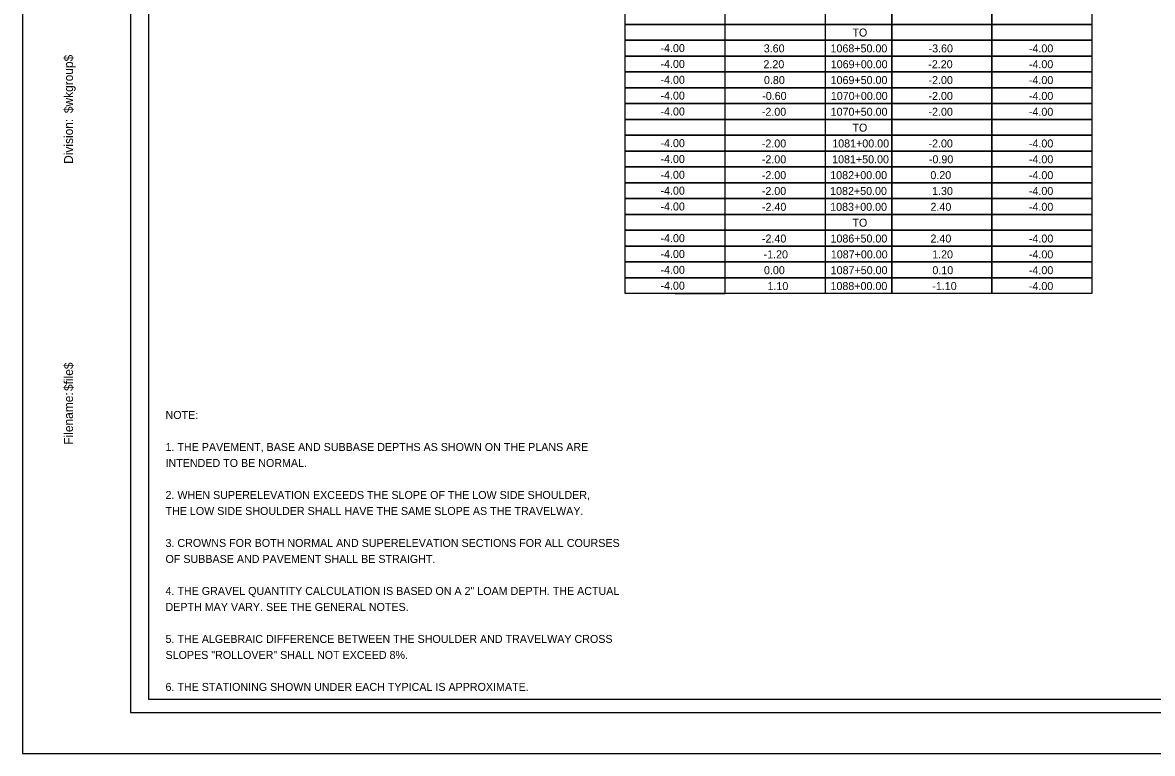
# Model space of a CAD drawing. Extents: x 1026502 to 1027102, y 781811 to 782040.
# Drawn here: x 1026618.9 to 1026686.7, y 781854.4 to 781898.3 of the extents above; entities that cross this region are included whole.
import ezdxf

# ---------------------------------------------------------------- set-up
doc = ezdxf.new("R2010")
doc.units = 0
for name, color, linetype in [('ANNOTATION', 7, 'Continuous'), ('BORDER', 7, 'Continuous'), ('DIMENSIONS', 7, 'Continuous'), ('JUNK', 7, 'Continuous'), ('PLOT BOUNDARY', 7, 'Continuous')]:
    doc.layers.add(name, color=color, linetype=linetype)

msp = doc.modelspace()

# ---------------------------------------------------------------- linework, layer by layer
at = {"layer": 'ANNOTATION'}
msp.add_lwpolyline([(1026655.027, 781936.19), (1026683.027, 781936.19), (1026683.027, 781882.017), (1026655.027, 781882.017)], close=True, dxfattribs=at)
at = {"layer": 'BORDER'}
for p, q in [((1026625.357, 781940.868), (1026625.357, 781856.868)), ((1026658.027, 781898.174), (1026655.027, 781898.174)), ((1026658.027, 781898.174), (1026655.027, 781898.174)), ((1026658.027, 781898.174), (1026661.027, 781898.174)), ((1026658.027, 781897.223), (1026655.027, 781897.223)), ((1026658.027, 781897.223), (1026655.027, 781897.223)), ((1026658.027, 781897.223), (1026661.027, 781897.223)), ((1026658.027, 781896.273), (1026655.027, 781896.273)), ((1026658.027, 781896.273), (1026655.027, 781896.273)), ((1026658.027, 781896.273), (1026661.027, 781896.273)), ((1026658.027, 781895.322), (1026655.027, 781895.322)), ((1026658.027, 781895.322), (1026655.027, 781895.322)), ((1026658.027, 781895.322), (1026661.027, 781895.322)), ((1026658.027, 781894.372), (1026655.027, 781894.372)), ((1026658.027, 781894.372), (1026655.027, 781894.372)), ((1026658.027, 781894.372), (1026661.027, 781894.372)), ((1026658.027, 781893.422), (1026655.027, 781893.422)), ((1026658.027, 781893.422), (1026655.027, 781893.422)), ((1026658.027, 781893.422), (1026661.027, 781893.422)), ((1026658.027, 781892.471), (1026655.027, 781892.471)), ((1026658.027, 781892.471), (1026655.027, 781892.471)), ((1026658.027, 781892.471), (1026661.027, 781892.471)), ((1026658.027, 781891.521), (1026655.027, 781891.521)), ((1026658.027, 781891.521), (1026655.027, 781891.521)), ((1026658.027, 781891.521), (1026661.027, 781891.521)), ((1026658.027, 781890.57), (1026655.027, 781890.57)), ((1026658.027, 781890.57), (1026655.027, 781890.57)), ((1026658.027, 781890.57), (1026661.027, 781890.57)), ((1026658.027, 781889.62), (1026655.027, 781889.62)), ((1026658.027, 781889.62), (1026655.027, 781889.62)), ((1026658.027, 781889.62), (1026661.027, 781889.62)), ((1026658.027, 781888.67), (1026655.027, 781888.67)), ((1026658.027, 781888.67), (1026655.027, 781888.67)), ((1026658.027, 781888.67), (1026661.027, 781888.67)), ((1026658.027, 781887.719), (1026655.027, 781887.719)), ((1026658.027, 781887.719), (1026655.027, 781887.719)), ((1026658.027, 781887.719), (1026661.027, 781887.719)), ((1026658.027, 781886.769), (1026655.027, 781886.769)), ((1026658.027, 781886.769), (1026655.027, 781886.769)), ((1026658.027, 781886.769), (1026661.027, 781886.769)), ((1026658.027, 781885.818), (1026655.027, 781885.818)), ((1026658.027, 781885.818), (1026655.027, 781885.818)), ((1026658.027, 781885.818), (1026661.027, 781885.818)), ((1026658.027, 781884.868), (1026655.027, 781884.868)), ((1026658.027, 781884.868), (1026655.027, 781884.868)), ((1026658.027, 781884.868), (1026661.027, 781884.868)), ((1026658.027, 781883.918), (1026655.027, 781883.918)), ((1026658.027, 781883.918), (1026655.027, 781883.918)), ((1026658.027, 781883.918), (1026661.027, 781883.918)), ((1026658.027, 781882.967), (1026655.027, 781882.967)), ((1026658.027, 781882.967), (1026655.027, 781882.967)), ((1026658.027, 781882.967), (1026661.027, 781882.967)), ((1026658.027, 781882.017), (1026655.027, 781882.017)), ((1026658.027, 781882.017), (1026655.027, 781882.017)), ((1026658.027, 781882.017), (1026661.027, 781882.017)), ((1026625.357, 781856.868), (1026753.357, 781856.868))]:
    msp.add_line(p, q, dxfattribs=at)
for points in [[(1026655.027, 781899.124), (1026683.027, 781899.124), (1026683.027, 781898.174), (1026655.027, 781898.174)], [(1026655.027, 781898.174), (1026683.027, 781898.174), (1026683.027, 781897.223), (1026655.027, 781897.223)], [(1026655.027, 781897.223), (1026683.027, 781897.223), (1026683.027, 781896.273), (1026655.027, 781896.273)], [(1026655.027, 781896.273), (1026683.027, 781896.273), (1026683.027, 781895.322), (1026655.027, 781895.322)], [(1026655.027, 781895.322), (1026683.027, 781895.322), (1026683.027, 781894.372), (1026655.027, 781894.372)], [(1026655.027, 781894.372), (1026683.027, 781894.372), (1026683.027, 781893.422), (1026655.027, 781893.422)], [(1026655.027, 781893.422), (1026683.027, 781893.422), (1026683.027, 781892.471), (1026655.027, 781892.471)], [(1026655.027, 781892.471), (1026683.027, 781892.471), (1026683.027, 781891.521), (1026655.027, 781891.521)], [(1026655.027, 781891.521), (1026683.027, 781891.521), (1026683.027, 781890.57), (1026655.027, 781890.57)], [(1026655.027, 781890.57), (1026683.027, 781890.57), (1026683.027, 781889.62), (1026655.027, 781889.62)], [(1026655.027, 781889.62), (1026683.027, 781889.62), (1026683.027, 781888.67), (1026655.027, 781888.67)], [(1026655.027, 781888.67), (1026683.027, 781888.67), (1026683.027, 781887.719), (1026655.027, 781887.719)], [(1026655.027, 781887.719), (1026683.027, 781887.719), (1026683.027, 781886.769), (1026655.027, 781886.769)], [(1026655.027, 781886.769), (1026683.027, 781886.769), (1026683.027, 781885.818), (1026655.027, 781885.818)], [(1026655.027, 781885.818), (1026683.027, 781885.818), (1026683.027, 781884.868), (1026655.027, 781884.868)], [(1026655.027, 781884.868), (1026683.027, 781884.868), (1026683.027, 781883.918), (1026655.027, 781883.918)], [(1026655.027, 781883.918), (1026683.027, 781883.918), (1026683.027, 781882.967), (1026655.027, 781882.967)], [(1026655.027, 781882.967), (1026683.027, 781882.967), (1026683.027, 781882.017), (1026655.027, 781882.017)]]:
    msp.add_lwpolyline(points, close=True, dxfattribs=at)
for points in [[(1026667.027, 781899.124), (1026667.027, 781898.174), (1026661.027, 781898.174), (1026661.027, 781899.124)], [(1026671.027, 781899.124), (1026671.027, 781898.174), (1026667.027, 781898.174)], [(1026677.027, 781899.124), (1026677.027, 781898.174), (1026671.027, 781898.174), (1026671.027, 781899.124)], [(1026683.027, 781899.124), (1026683.027, 781898.174), (1026677.027, 781898.174), (1026677.027, 781899.124)], [(1026667.027, 781898.174), (1026667.027, 781897.223), (1026661.027, 781897.223), (1026661.027, 781898.174)], [(1026671.027, 781898.174), (1026671.027, 781897.223), (1026667.027, 781897.223)], [(1026677.027, 781898.174), (1026677.027, 781897.223), (1026671.027, 781897.223), (1026671.027, 781898.174)], [(1026683.027, 781898.174), (1026683.027, 781897.223), (1026677.027, 781897.223), (1026677.027, 781898.174)], [(1026667.027, 781897.223), (1026667.027, 781896.273), (1026661.027, 781896.273), (1026661.027, 781897.223)], [(1026671.027, 781897.223), (1026671.027, 781896.273), (1026667.027, 781896.273)], [(1026677.027, 781897.223), (1026677.027, 781896.273), (1026671.027, 781896.273), (1026671.027, 781897.223)], [(1026683.027, 781897.223), (1026683.027, 781896.273), (1026677.027, 781896.273), (1026677.027, 781897.223)], [(1026667.027, 781896.273), (1026667.027, 781895.322), (1026661.027, 781895.322), (1026661.027, 781896.273)], [(1026671.027, 781896.273), (1026671.027, 781895.322), (1026667.027, 781895.322)], [(1026677.027, 781896.273), (1026677.027, 781895.322), (1026671.027, 781895.322), (1026671.027, 781896.273)], [(1026683.027, 781896.273), (1026683.027, 781895.322), (1026677.027, 781895.322), (1026677.027, 781896.273)], [(1026667.027, 781895.322), (1026667.027, 781894.372), (1026661.027, 781894.372), (1026661.027, 781895.322)], [(1026671.027, 781895.322), (1026671.027, 781894.372), (1026667.027, 781894.372)], [(1026677.027, 781895.322), (1026677.027, 781894.372), (1026671.027, 781894.372), (1026671.027, 781895.322)], [(1026683.027, 781895.322), (1026683.027, 781894.372), (1026677.027, 781894.372), (1026677.027, 781895.322)], [(1026667.027, 781894.372), (1026667.027, 781893.422), (1026661.027, 781893.422), (1026661.027, 781894.372)], [(1026671.027, 781894.372), (1026671.027, 781893.422), (1026667.027, 781893.422)], [(1026677.027, 781894.372), (1026677.027, 781893.422), (1026671.027, 781893.422), (1026671.027, 781894.372)], [(1026683.027, 781894.372), (1026683.027, 781893.422), (1026677.027, 781893.422), (1026677.027, 781894.372)], [(1026667.027, 781893.422), (1026667.027, 781892.471), (1026661.027, 781892.471), (1026661.027, 781893.422)], [(1026671.027, 781893.422), (1026671.027, 781892.471), (1026667.027, 781892.471)], [(1026677.027, 781893.422), (1026677.027, 781892.471), (1026671.027, 781892.471), (1026671.027, 781893.422)], [(1026683.027, 781893.422), (1026683.027, 781892.471), (1026677.027, 781892.471), (1026677.027, 781893.422)], [(1026667.027, 781892.471), (1026667.027, 781891.521), (1026661.027, 781891.521), (1026661.027, 781892.471)], [(1026671.027, 781892.471), (1026671.027, 781891.521), (1026667.027, 781891.521)], [(1026677.027, 781892.471), (1026677.027, 781891.521), (1026671.027, 781891.521), (1026671.027, 781892.471)], [(1026683.027, 781892.471), (1026683.027, 781891.521), (1026677.027, 781891.521), (1026677.027, 781892.471)], [(1026667.027, 781891.521), (1026667.027, 781890.57), (1026661.027, 781890.57), (1026661.027, 781891.521)], [(1026671.027, 781891.521), (1026671.027, 781890.57), (1026667.027, 781890.57)], [(1026677.027, 781891.521), (1026677.027, 781890.57), (1026671.027, 781890.57), (1026671.027, 781891.521)], [(1026683.027, 781891.521), (1026683.027, 781890.57), (1026677.027, 781890.57), (1026677.027, 781891.521)], [(1026667.027, 781890.57), (1026667.027, 781889.62), (1026661.027, 781889.62), (1026661.027, 781890.57)], [(1026671.027, 781890.57), (1026671.027, 781889.62), (1026667.027, 781889.62)], [(1026677.027, 781890.57), (1026677.027, 781889.62), (1026671.027, 781889.62), (1026671.027, 781890.57)], [(1026683.027, 781890.57), (1026683.027, 781889.62), (1026677.027, 781889.62), (1026677.027, 781890.57)], [(1026667.027, 781889.62), (1026667.027, 781888.67), (1026661.027, 781888.67), (1026661.027, 781889.62)], [(1026671.027, 781889.62), (1026671.027, 781888.67), (1026667.027, 781888.67)], [(1026677.027, 781889.62), (1026677.027, 781888.67), (1026671.027, 781888.67), (1026671.027, 781889.62)], [(1026683.027, 781889.62), (1026683.027, 781888.67), (1026677.027, 781888.67), (1026677.027, 781889.62)], [(1026667.027, 781888.67), (1026667.027, 781887.719), (1026661.027, 781887.719), (1026661.027, 781888.67)], [(1026671.027, 781888.67), (1026671.027, 781887.719), (1026667.027, 781887.719)], [(1026677.027, 781888.67), (1026677.027, 781887.719), (1026671.027, 781887.719), (1026671.027, 781888.67)], [(1026683.027, 781888.67), (1026683.027, 781887.719), (1026677.027, 781887.719), (1026677.027, 781888.67)], [(1026667.027, 781887.719), (1026667.027, 781886.769), (1026661.027, 781886.769), (1026661.027, 781887.719)], [(1026671.027, 781887.719), (1026671.027, 781886.769), (1026667.027, 781886.769)], [(1026677.027, 781887.719), (1026677.027, 781886.769), (1026671.027, 781886.769), (1026671.027, 781887.719)], [(1026683.027, 781887.719), (1026683.027, 781886.769), (1026677.027, 781886.769), (1026677.027, 781887.719)], [(1026667.027, 781886.769), (1026667.027, 781885.818), (1026661.027, 781885.818), (1026661.027, 781886.769)], [(1026671.027, 781886.769), (1026671.027, 781885.818), (1026667.027, 781885.818)], [(1026677.027, 781886.769), (1026677.027, 781885.818), (1026671.027, 781885.818), (1026671.027, 781886.769)], [(1026683.027, 781886.769), (1026683.027, 781885.818), (1026677.027, 781885.818), (1026677.027, 781886.769)], [(1026667.027, 781885.818), (1026667.027, 781884.868), (1026661.027, 781884.868), (1026661.027, 781885.818)], [(1026671.027, 781885.818), (1026671.027, 781884.868), (1026667.027, 781884.868)], [(1026677.027, 781885.818), (1026677.027, 781884.868), (1026671.027, 781884.868), (1026671.027, 781885.818)], [(1026683.027, 781885.818), (1026683.027, 781884.868), (1026677.027, 781884.868), (1026677.027, 781885.818)], [(1026667.027, 781884.868), (1026667.027, 781883.918), (1026661.027, 781883.918), (1026661.027, 781884.868)], [(1026671.027, 781884.868), (1026671.027, 781883.918), (1026667.027, 781883.918)], [(1026677.027, 781884.868), (1026677.027, 781883.918), (1026671.027, 781883.918), (1026671.027, 781884.868)], [(1026683.027, 781884.868), (1026683.027, 781883.918), (1026677.027, 781883.918), (1026677.027, 781884.868)], [(1026667.027, 781883.918), (1026667.027, 781882.967), (1026661.027, 781882.967), (1026661.027, 781883.918)], [(1026671.027, 781883.918), (1026671.027, 781882.967), (1026667.027, 781882.967)], [(1026677.027, 781883.918), (1026677.027, 781882.967), (1026671.027, 781882.967), (1026671.027, 781883.918)], [(1026683.027, 781883.918), (1026683.027, 781882.967), (1026677.027, 781882.967), (1026677.027, 781883.918)], [(1026667.027, 781882.967), (1026667.027, 781882.017), (1026661.027, 781882.017), (1026661.027, 781882.967)], [(1026671.027, 781882.967), (1026671.027, 781882.017), (1026667.027, 781882.017)], [(1026677.027, 781882.967), (1026677.027, 781882.017), (1026671.027, 781882.017), (1026671.027, 781882.967)], [(1026683.027, 781882.967), (1026683.027, 781882.017), (1026677.027, 781882.017), (1026677.027, 781882.967)]]:
    msp.add_lwpolyline(points, dxfattribs=at)
at = {"layer": 'JUNK'}
msp.add_lwpolyline([(1026626.458, 781939.919), (1026744.596, 781939.919), (1026744.596, 781857.651), (1026626.458, 781857.651)], close=True, dxfattribs=at)
at = {"layer": 'PLOT BOUNDARY'}
msp.add_lwpolyline([(1026618.883, 781854.421), (1026754.882, 781854.421), (1026754.882, 781942.421), (1026618.883, 781942.421)], close=True, dxfattribs=at)

# ---------------------------------------------------------------- texts
at = {"layer": 'ANNOTATION'}
for s, p in [('NOTE:', (1026627.458, 781874.491)), ('1. THE PAVEMENT, BASE AND SUBBASE DEPTHS AS SHOWN ON THE PLANS ARE', (1026627.458, 781872.571)), ('INTENDED TO BE NORMAL.', (1026627.458, 781871.611)), ('2. WHEN SUPERELEVATION EXCEEDS THE SLOPE OF THE LOW SIDE SHOULDER,', (1026627.458, 781869.691)), ('THE LOW SIDE SHOULDER SHALL HAVE THE SAME SLOPE AS THE TRAVELWAY.', (1026627.458, 781868.731)), ('3. CROWNS FOR BOTH NORMAL AND SUPERELEVATION SECTIONS FOR ALL COURSES', (1026627.458, 781866.811)), ('OF SUBBASE AND PAVEMENT SHALL BE STRAIGHT.', (1026627.458, 781865.851)), ('4. THE GRAVEL QUANTITY CALCULATION IS BASED ON A 2" LOAM DEPTH. THE ACTUAL', (1026627.458, 781863.931)), ('DEPTH MAY VARY. SEE THE GENERAL NOTES.', (1026627.458, 781862.971)), ('5. THE ALGEBRAIC DIFFERENCE BETWEEN THE SHOULDER AND TRAVELWAY CROSS', (1026627.458, 781861.051)), ('SLOPES "ROLLOVER" SHALL NOT EXCEED 8%.', (1026627.458, 781860.091)), ('6. THE STATIONING SHOWN UNDER EACH TYPICAL IS APPROXIMATE.', (1026627.458, 781858.171))]:
    msp.add_text(s, height=0.48, dxfattribs=at).set_placement(p)
at = {"layer": 'BORDER'}
for s, p in [('$wkgroup$', (1026621.905, 781892.844)), ('Division:', (1026621.905, 781889.801)), ('$file$', (1026621.905, 781876.169)), ('Filename:', (1026621.905, 781872.947))]:
    msp.add_text(s, height=0.5357, rotation=90, dxfattribs=at).set_placement(p)
at = {"layer": 'DIMENSIONS'}
for s, p in [('TO', (1026668.669, 781897.442)), ('-4.00', (1026657.154, 781896.508)), ('3.60', (1026663.351, 781896.491)), ('1068+50.00', (1026667.354, 781896.491)), ('-3.60', (1026673.238, 781896.491)), ('-4.00', (1026679.257, 781896.491)), ('-4.00', (1026657.154, 781895.558)), ('2.20', (1026663.332, 781895.54)), ('1069+00.00', (1026667.369, 781895.54)), ('-2.20', (1026673.219, 781895.54)), ('-4.00', (1026679.257, 781895.54)), ('-4.00', (1026657.154, 781894.607)), ('0.80', (1026663.362, 781894.59)), ('1069+50.00', (1026667.361, 781894.59)), ('-2.00', (1026673.234, 781894.59)), ('-4.00', (1026679.257, 781894.59)), ('-4.00', (1026657.154, 781893.657)), ('-0.60', (1026663.257, 781893.639)), ('1070+00.00', (1026667.373, 781893.639)), ('-2.00', (1026673.234, 781893.639)), ('-4.00', (1026679.257, 781893.639)), ('-4.00', (1026657.154, 781892.706)), ('-2.00', (1026663.234, 781892.688)), ('1070+50.00', (1026667.365, 781892.688)), ('-2.00', (1026673.234, 781892.688)), ('-4.00', (1026679.257, 781892.688)), ('TO', (1026668.669, 781891.737)), ('-4.00', (1026657.154, 781890.806)), ('-2.00', (1026663.234, 781890.786)), ('1081+00.00', (1026667.46, 781890.786)), ('-2.00', (1026673.234, 781890.786)), ('-4.00', (1026679.257, 781890.786)), ('-4.00', (1026657.154, 781889.855)), ('-2.00', (1026663.234, 781889.835)), ('1081+50.00', (1026667.452, 781889.835)), ('-0.90', (1026673.257, 781889.835)), ('-4.00', (1026679.257, 781889.835)), ('-4.00', (1026657.154, 781888.905)), ('-2.00', (1026663.234, 781888.885)), ('1082+00.00', (1026667.339, 781888.885)), ('0.20', (1026673.347, 781888.885)), ('-4.00', (1026679.257, 781888.885)), ('-4.00', (1026657.154, 781887.954)), ('-2.00', (1026663.234, 781887.934)), ('1082+50.00', (1026667.331, 781887.934)), ('1.30', (1026673.449, 781887.934)), ('-4.00', (1026679.257, 781887.934)), ('-4.00', (1026657.154, 781887.004)), ('-2.40', (1026663.242, 781886.983)), ('1083+00.00', (1026667.335, 781886.983)), ('2.40', (1026673.355, 781886.983)), ('-4.00', (1026679.257, 781886.983)), ('TO', (1026668.669, 781886.032)), ('-4.00', (1026657.154, 781885.103)), ('-2.40', (1026663.242, 781885.081)), ('1086+50.00', (1026667.354, 781885.081)), ('2.40', (1026673.355, 781885.081)), ('-4.00', (1026679.257, 781885.081)), ('-4.00', (1026657.154, 781884.153)), ('-1.20', (1026663.34, 781884.13)), ('1087+00.00', (1026667.373, 781884.13)), ('1.20', (1026673.453, 781884.13)), ('-4.00', (1026679.257, 781884.13)), ('-4.00', (1026657.154, 781883.202)), ('0.00', (1026663.362, 781883.18)), ('1087+50.00', (1026667.365, 781883.18)), ('0.10', (1026673.468, 781883.18)), ('-4.00', (1026679.257, 781883.18)), ('-4.00', (1026657.154, 781882.252)), ('1.10', (1026663.574, 781882.229)), ('1088+00.00', (1026667.354, 781882.229)), ('-1.10', (1026673.461, 781882.229)), ('-4.00', (1026679.257, 781882.229))]:
    msp.add_text(s, height=0.48, dxfattribs=at).set_placement(p)

doc.saveas('drawing.dxf')
